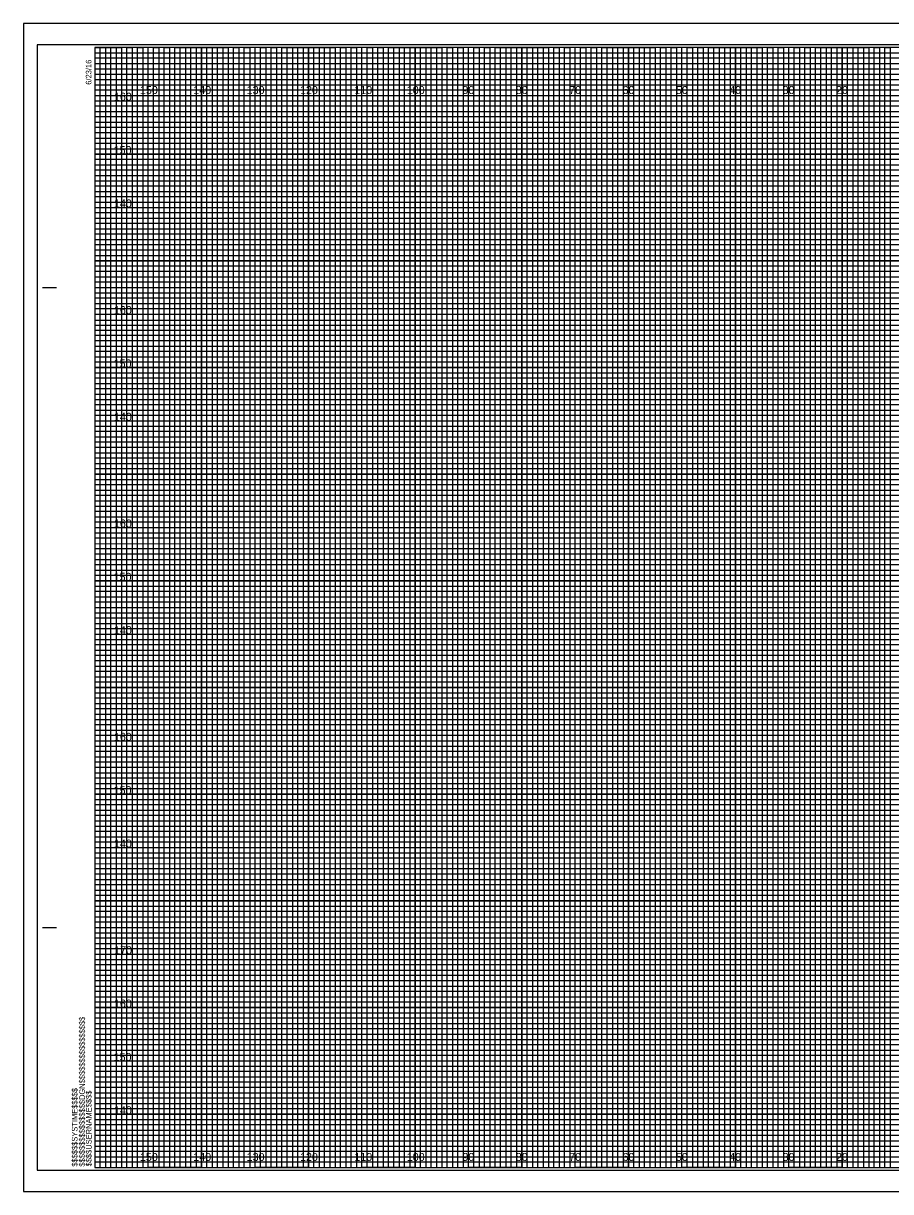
# Model space of a CAD drawing. Extents: x -13 to 323, y -5 to 4834.
# Drawn here: x -13.4 to 149.1, y 1315.5 to 1534.5 of the extents above; entities that cross this region are included whole.
import ezdxf

# ---------------------------------------------------------------- set-up
doc = ezdxf.new("R2010")
doc.units = 0
for name, color, linetype in [('Exist Cross Section Cell', 7, 'Continuous'), ('Exist XS Center Line Elevation Label', 7, 'Continuous'), ('Exist XS Ground Line', 7, 'Continuous'), ('Prop CMT Pvmt Course 1', 7, 'Continuous'), ('Prop CMT Pvmt Course 2', 7, 'Continuous'), ('Prop CMT Pvmt Course 3', 7, 'Continuous'), ('Prop CMT Pvmt Surface Shoulder', 7, 'Continuous'), ('Prop CMT Shld Paved Course 1', 7, 'Continuous'), ('Prop CMT Shld Paved Course 2', 7, 'Continuous'), ('Prop CMT Shld Paved Course 3', 7, 'Continuous'), ('Prop CMT Slope Grass', 7, 'Continuous')]:
    doc.layers.add(name, color=color, linetype=linetype)

msp = doc.modelspace()

# ---------------------------------------------------------------- linework, layer by layer
at = {"layer": 'Exist XS Center Line Elevation Label'}
for points in [[(0, 1530), (5, 1530), (5, 1320), (15, 1320), (15, 1530), (25, 1530), (25, 1320), (35, 1320), (35, 1530), (45, 1530), (45, 1320), (55, 1320), (55, 1530), (65, 1530), (65, 1320), (75, 1320), (75, 1530), (85, 1530), (85, 1320), (95, 1320), (95, 1530), (105, 1530), (105, 1320), (115, 1320), (115, 1530), (125, 1530), (125, 1320), (135, 1320), (135, 1530), (145, 1530), (145, 1320), (155, 1320)], [(0, 1525), (275, 1525)], [(0, 1505), (320, 1505), (320, 1515), (0, 1515)], [(0, 1485), (320, 1485), (320, 1495), (0, 1495)], [(0, 1465), (320, 1465), (320, 1475), (0, 1475)], [(0, 1445), (320, 1445), (320, 1455), (0, 1455)], [(0, 1425), (320, 1425), (320, 1435), (0, 1435)], [(0, 1405), (320, 1405), (320, 1415), (0, 1415)], [(0, 1385), (320, 1385), (320, 1395), (0, 1395)], [(0, 1365), (320, 1365), (320, 1375), (0, 1375)], [(0, 1345), (320, 1345), (320, 1355), (0, 1355)], [(0, 1325), (320, 1325), (320, 1335), (0, 1335)]]:
    msp.add_lwpolyline(points, dxfattribs=at)
at = {"layer": 'Exist XS Ground Line'}
for p, q in [((10, 1530), (0, 1530)), ((10, 1320), (10, 1530)), ((30, 1530), (20, 1530)), ((20, 1530), (20, 1320)), ((30, 1320), (30, 1530)), ((50, 1530), (40, 1530)), ((40, 1530), (40, 1320)), ((50, 1320), (50, 1530)), ((70, 1530), (60, 1530)), ((60, 1530), (60, 1320)), ((70, 1320), (70, 1530)), ((90, 1530), (80, 1530)), ((80, 1530), (80, 1320)), ((90, 1320), (90, 1530)), ((110, 1530), (100, 1530)), ((100, 1530), (100, 1320)), ((110, 1320), (110, 1530)), ((130, 1530), (120, 1530)), ((120, 1530), (120, 1320)), ((130, 1320), (130, 1530)), ((150, 1530), (140, 1530)), ((140, 1530), (140, 1320)), ((20, 1320), (10, 1320)), ((40, 1320), (30, 1320)), ((60, 1320), (50, 1320)), ((80, 1320), (70, 1320)), ((100, 1320), (90, 1320)), ((120, 1320), (110, 1320)), ((140, 1320), (130, 1320))]:
    msp.add_line(p, q, dxfattribs=at)
for points in [[(0, 1520), (320, 1520), (320, 1510), (0, 1510)], [(0, 1500), (320, 1500), (320, 1490), (0, 1490)], [(0, 1480), (320, 1480), (320, 1470), (0, 1470)], [(0, 1460), (320, 1460), (320, 1450), (0, 1450)], [(0, 1440), (320, 1440), (320, 1430), (0, 1430)], [(0, 1420), (320, 1420), (320, 1410), (0, 1410)], [(0, 1400), (320, 1400), (320, 1390), (0, 1390)], [(0, 1380), (320, 1380), (320, 1370), (0, 1370)], [(0, 1360), (320, 1360), (320, 1350), (0, 1350)], [(0, 1340), (320, 1340), (320, 1330), (0, 1330)]]:
    msp.add_lwpolyline(points, dxfattribs=at)
at = {"layer": 'Prop CMT Pvmt Course 1'}
for points in [[(0, 1320), (1, 1320), (1, 1530), (2, 1530), (2, 1320)], [(2, 1320), (3, 1320), (3, 1530), (4, 1530), (4, 1320)], [(5, 1320), (6, 1320), (6, 1530), (7, 1530), (7, 1320)], [(7, 1320), (8, 1320), (8, 1530), (9, 1530), (9, 1320)], [(10, 1320), (11, 1320), (11, 1530), (12, 1530), (12, 1320)], [(12, 1320), (13, 1320), (13, 1530), (14, 1530), (14, 1320)], [(15, 1320), (16, 1320), (16, 1530), (17, 1530), (17, 1320)], [(17, 1320), (18, 1320), (18, 1530), (19, 1530), (19, 1320)], [(20, 1320), (21, 1320), (21, 1530), (22, 1530), (22, 1320)], [(22, 1320), (23, 1320), (23, 1530), (24, 1530), (24, 1320)], [(25, 1320), (26, 1320), (26, 1530), (27, 1530), (27, 1320)], [(27, 1320), (28, 1320), (28, 1530), (29, 1530), (29, 1320)], [(30, 1320), (31, 1320), (31, 1530), (32, 1530), (32, 1320)], [(32, 1320), (33, 1320), (33, 1530), (34, 1530), (34, 1320)], [(35, 1320), (36, 1320), (36, 1530), (37, 1530), (37, 1320)], [(37, 1320), (38, 1320), (38, 1530), (39, 1530), (39, 1320)], [(40, 1320), (41, 1320), (41, 1530), (42, 1530), (42, 1320)], [(42, 1320), (43, 1320), (43, 1530), (44, 1530), (44, 1320)], [(45, 1320), (46, 1320), (46, 1530), (47, 1530), (47, 1320)], [(47, 1320), (48, 1320), (48, 1530), (49, 1530), (49, 1320)], [(50, 1320), (51, 1320), (51, 1530), (52, 1530), (52, 1320)], [(52, 1320), (53, 1320), (53, 1530), (54, 1530), (54, 1320)], [(55, 1320), (56, 1320), (56, 1530), (57, 1530), (57, 1320)], [(57, 1320), (58, 1320), (58, 1530), (59, 1530), (59, 1320)], [(60, 1320), (61, 1320), (61, 1530), (62, 1530), (62, 1320)], [(62, 1320), (63, 1320), (63, 1530), (64, 1530), (64, 1320)], [(65, 1320), (66, 1320), (66, 1530), (67, 1530), (67, 1320)], [(67, 1320), (68, 1320), (68, 1530), (69, 1530), (69, 1320)], [(70, 1320), (71, 1320), (71, 1530), (72, 1530), (72, 1320)], [(72, 1320), (73, 1320), (73, 1530), (74, 1530), (74, 1320)], [(75, 1320), (76, 1320), (76, 1530), (77, 1530), (77, 1320)], [(77, 1320), (78, 1320), (78, 1530), (79, 1530), (79, 1320)], [(80, 1320), (81, 1320), (81, 1530), (82, 1530), (82, 1320)], [(82, 1320), (83, 1320), (83, 1530), (84, 1530), (84, 1320)], [(85, 1320), (86, 1320), (86, 1530), (87, 1530), (87, 1320)], [(87, 1320), (88, 1320), (88, 1530), (89, 1530), (89, 1320)], [(90, 1320), (91, 1320), (91, 1530), (92, 1530), (92, 1320)], [(92, 1320), (93, 1320), (93, 1530), (94, 1530), (94, 1320)], [(95, 1320), (96, 1320), (96, 1530), (97, 1530), (97, 1320)], [(97, 1320), (98, 1320), (98, 1530), (99, 1530), (99, 1320)], [(100, 1320), (101, 1320), (101, 1530), (102, 1530), (102, 1320)], [(102, 1320), (103, 1320), (103, 1530), (104, 1530), (104, 1320)], [(105, 1320), (106, 1320), (106, 1530), (107, 1530), (107, 1320)], [(107, 1320), (108, 1320), (108, 1530), (109, 1530), (109, 1320)], [(110, 1320), (111, 1320), (111, 1530), (112, 1530), (112, 1320)], [(112, 1320), (113, 1320), (113, 1530), (114, 1530), (114, 1320)], [(115, 1320), (116, 1320), (116, 1530), (117, 1530), (117, 1320)], [(117, 1320), (118, 1320), (118, 1530), (119, 1530), (119, 1320)], [(120, 1320), (121, 1320), (121, 1530), (122, 1530), (122, 1320)], [(122, 1320), (123, 1320), (123, 1530), (124, 1530), (124, 1320)], [(125, 1320), (126, 1320), (126, 1530), (127, 1530), (127, 1320)], [(127, 1320), (128, 1320), (128, 1530), (129, 1530), (129, 1320)], [(130, 1320), (131, 1320), (131, 1530), (132, 1530), (132, 1320)], [(132, 1320), (133, 1320), (133, 1530), (134, 1530), (134, 1320)], [(135, 1320), (136, 1320), (136, 1530), (137, 1530), (137, 1320)], [(137, 1320), (138, 1320), (138, 1530), (139, 1530), (139, 1320)], [(140, 1320), (141, 1320), (141, 1530), (142, 1530), (142, 1320)], [(142, 1320), (143, 1320), (143, 1530), (144, 1530), (144, 1320)], [(145, 1320), (146, 1320), (146, 1530), (147, 1530), (147, 1320)], [(147, 1320), (148, 1320), (148, 1530), (149, 1530), (149, 1320)]]:
    msp.add_lwpolyline(points, dxfattribs=at)
at = {"layer": 'Prop CMT Pvmt Course 2'}
for p, q in [((323.3, 1534.5), (-13.4, 1534.5)), ((-13.4, 1534.5), (-13.4, 1315.5)), ((-13.4, 1315.5), (323.3, 1315.5))]:
    msp.add_line(p, q, dxfattribs=at)
at = {"layer": 'Prop CMT Pvmt Surface Shoulder'}
for p, q in [((-9.8, 1485), (-7.3, 1485)), ((-9.7, 1485), (-7.2, 1485)), ((-9.8, 1365), (-7.3, 1365)), ((-9.7, 1365), (-7.2, 1365)), ((0, 1320), (0, 1320)), ((0, 1320), (0, 1320)), ((0, 1320), (0, 1320)), ((0, 1320), (0, 1320)), ((0, 1320), (0, 1320)), ((0, 1320), (0, 1320)), ((0, 1320), (0, 1320))]:
    msp.add_line(p, q, dxfattribs=at)
msp.add_lwpolyline([(320, 1530), (0, 1530), (0, 1320), (320, 1320)], close=True, dxfattribs=at)
at = {"layer": 'Prop CMT Shld Paved Course 1'}
msp.add_lwpolyline([(-13.4, 1315.5), (323.3, 1315.5), (323.3, 1534.5), (-13.4, 1534.5)], close=True, dxfattribs=at)
at = {"layer": 'Prop CMT Shld Paved Course 2'}
msp.add_lwpolyline([(-10.8, 1319.5), (322.4, 1319.5), (322.4, 1530.5), (-10.8, 1530.5)], close=True, dxfattribs=at)
at = {"layer": 'Prop CMT Shld Paved Course 3'}
for p, q in [((10, 1320), (10, 1530)), ((20, 1320), (20, 1530)), ((30, 1320), (30, 1530)), ((40, 1320), (40, 1530)), ((50, 1320), (50, 1530)), ((60, 1320), (60, 1530)), ((70, 1320), (70, 1530)), ((80, 1320), (80, 1530)), ((90, 1320), (90, 1530)), ((100, 1320), (100, 1530)), ((110, 1320), (110, 1530)), ((120, 1320), (120, 1530)), ((130, 1320), (130, 1530)), ((140, 1320), (140, 1530)), ((0, 1520), (320, 1520)), ((0, 1510), (320, 1510)), ((0, 1500), (320, 1500)), ((0, 1490), (320, 1490)), ((0, 1480), (320, 1480)), ((0, 1470), (320, 1470)), ((0, 1460), (320, 1460)), ((0, 1450), (320, 1450)), ((0, 1440), (320, 1440)), ((0, 1430), (320, 1430)), ((0, 1420), (320, 1420)), ((0, 1410), (320, 1410)), ((0, 1400), (320, 1400)), ((0, 1390), (320, 1390)), ((0, 1380), (320, 1380)), ((0, 1370), (320, 1370)), ((0, 1360), (320, 1360)), ((0, 1350), (320, 1350)), ((0, 1340), (320, 1340)), ((0, 1330), (320, 1330))]:
    msp.add_line(p, q, dxfattribs=at)
at = {"layer": 'Prop CMT Slope Grass'}
for p, q in [((0, 1529), (260, 1529)), ((260, 1527.98), (0, 1527.98)), ((0, 1527.98), (0, 1527)), ((0, 1527), (260, 1527)), ((260, 1525.89), (0, 1525.89)), ((0, 1525.89), (0, 1524)), ((0, 1524), (320, 1524))]:
    msp.add_line(p, q, dxfattribs=at)
for points in [[(0, 1523), (270, 1523), (320, 1523), (320, 1522), (0, 1522)], [(0, 1521), (320, 1521), (320, 1519), (0, 1519)], [(0, 1518), (320, 1518), (320, 1517), (0, 1516.98)], [(0, 1516), (320, 1516), (320, 1514), (0, 1514)], [(0, 1513), (320, 1513), (320, 1512), (0, 1512)], [(0, 1511), (320, 1511), (320, 1509), (0, 1509)], [(0, 1508), (320, 1508), (320, 1507), (0, 1507)], [(0, 1506), (320, 1506), (320, 1504), (0, 1504)], [(0, 1503), (320, 1503), (320, 1502), (0, 1502)], [(0, 1501), (320, 1501), (320, 1499), (0, 1499)], [(0, 1498), (320, 1498), (320, 1497), (0, 1497)], [(0, 1496), (320, 1496), (320, 1493.95), (320, 1493), (320, 1492), (0, 1492)], [(0, 1494), (320, 1494), (320, 1493), (0, 1493)], [(0, 1491), (320, 1491), (320, 1489), (0, 1489.03)], [(0, 1489.03), (320, 1489), (320, 1488), (0, 1488)], [(0, 1487), (320, 1487), (320, 1486), (0, 1486)], [(0, 1484), (320, 1484), (320, 1483), (0, 1483)], [(0, 1482), (320, 1482), (320, 1481), (0, 1481)], [(-0.07, 1478.89), (320, 1478.89), (320, 1477.88), (-0.07, 1477.88)], [(0, 1477), (320, 1477), (320, 1476), (0, 1476)], [(0, 1474), (320, 1474), (320, 1473), (0, 1473)], [(0, 1472), (320, 1472), (320, 1471), (0, 1471)], [(0, 1469), (320, 1469), (320, 1468), (0, 1468)], [(0, 1467), (320, 1467), (320, 1466), (0, 1466)], [(0, 1464), (320, 1464), (320, 1463), (0, 1463)], [(0, 1462), (320, 1462), (320, 1461), (0, 1461)], [(0, 1459), (320, 1459), (319.99, 1457.98), (0, 1458)], [(0, 1457), (320, 1457), (320, 1456), (0, 1456)], [(0, 1454), (320, 1454), (320, 1453), (0, 1453)], [(0, 1452), (320, 1452), (320, 1451), (0, 1451)], [(0, 1449), (320, 1449), (320, 1448), (0, 1448)], [(0, 1447), (320, 1447), (320, 1446), (0, 1446)], [(0, 1444), (320, 1444), (320, 1443), (0, 1443)], [(0, 1442), (320, 1442), (320, 1441), (0, 1441)], [(0, 1439), (320, 1439), (320, 1438), (0, 1438)], [(0, 1436.99), (320.07, 1436.91), (320, 1436), (0, 1436)], [(0, 1434), (320, 1434), (320, 1433), (0, 1433)], [(0, 1432), (320, 1432), (320, 1431), (0, 1431)], [(0, 1429), (320, 1429), (320, 1428), (0, 1428)], [(0, 1427), (320, 1427), (320, 1426), (0, 1426)], [(0, 1424), (320, 1424), (320, 1423), (0, 1423)], [(0, 1422), (320, 1422), (320, 1421), (0, 1421)], [(0, 1419), (320, 1419), (320, 1418), (0, 1418)], [(0, 1417), (320, 1417), (320, 1416), (0, 1416)], [(0, 1414), (320, 1414), (320, 1413), (0, 1413)], [(0, 1412), (320, 1412), (320, 1411), (0, 1411)], [(0, 1409), (320, 1409), (320, 1408), (0, 1408)], [(0, 1407), (320, 1407), (320, 1406), (0, 1406)], [(0, 1404), (320, 1404), (320, 1403), (0, 1403)], [(0, 1402), (320, 1402), (320, 1401), (0, 1401)], [(0, 1399), (320, 1399), (319.99, 1397.98), (0, 1398)], [(0, 1397), (320, 1397), (320, 1396), (0, 1396)], [(0, 1394), (320, 1394), (320, 1393), (0, 1393)], [(0, 1392), (320, 1392), (320, 1391), (0, 1391)], [(0, 1389), (320, 1389), (320, 1388), (0, 1388)], [(0, 1387), (320, 1387), (320, 1386), (0, 1386)], [(0, 1384), (320, 1384), (320, 1383), (0, 1383)], [(0, 1382), (320, 1382), (320, 1381), (0, 1381)], [(0, 1379), (320, 1379), (320, 1378), (0, 1378)], [(0, 1376.99), (320.07, 1376.91), (320, 1376), (0, 1376)], [(0, 1374), (320, 1374), (320, 1373), (0, 1373)], [(0, 1372), (320, 1372), (320, 1371), (0, 1371)], [(0, 1369), (320, 1369), (320, 1368), (0, 1368)], [(0, 1367), (320, 1367), (320, 1366), (0, 1366)], [(0, 1364), (320, 1364), (320, 1363), (0, 1363)], [(0, 1362), (320, 1362), (320, 1361), (0, 1361)], [(0, 1359), (320, 1359), (320, 1358), (0, 1358)], [(0, 1357), (320, 1357), (320, 1356), (0, 1356)], [(0, 1354), (320, 1354), (320, 1353), (0, 1353)], [(0, 1352), (320, 1352), (320, 1351), (0, 1351)], [(0, 1349), (320, 1349), (320, 1348), (0, 1348)], [(0, 1347), (320, 1347), (320, 1346), (0, 1346)], [(0, 1344), (320, 1344), (320, 1343), (0, 1343)], [(0, 1342), (320, 1342), (320, 1341), (0, 1341)], [(0, 1339), (320, 1339), (320, 1338), (0, 1338)], [(0, 1337), (320, 1337), (320, 1336), (0, 1336)], [(0, 1334), (320, 1334), (320, 1333), (0, 1333)], [(0, 1332), (320, 1332), (320, 1331), (0, 1331)], [(0, 1329), (320, 1329), (320, 1328), (0, 1328)], [(0, 1327), (320, 1327), (320, 1326), (0, 1326)], [(0, 1324), (320, 1324), (320, 1323), (0, 1323)], [(0, 1322), (320, 1322), (320, 1321), (0, 1321)]]:
    msp.add_lwpolyline(points, dxfattribs=at)

# ---------------------------------------------------------------- texts
at = {"layer": 'Exist Cross Section Cell'}
for s, p in [('150', (8.44, 1521.25)), ('140', (18.44, 1521.25)), ('130', (28.44, 1521.25)), ('120', (38.44, 1521.25)), ('110', (48.62, 1521.25)), ('100', (58.44, 1521.25)), ('90', (68.86, 1521.25)), ('80', (78.86, 1521.25)), ('70', (88.86, 1521.25)), ('60', (98.86, 1521.25)), ('50', (108.86, 1521.25)), ('40', (118.86, 1521.25)), ('30', (128.86, 1521.25)), ('20', (138.86, 1521.25)), ('150', (8.44, 1321.25)), ('140', (18.44, 1321.25)), ('130', (28.44, 1321.25)), ('120', (38.44, 1321.25)), ('110', (48.62, 1321.25)), ('100', (58.44, 1321.25)), ('90', (68.86, 1321.25)), ('80', (78.86, 1321.25)), ('70', (88.86, 1321.25)), ('60', (98.86, 1321.25)), ('50', (108.86, 1321.25)), ('40', (118.86, 1321.25)), ('30', (128.86, 1321.25)), ('20', (138.86, 1321.25))]:
    msp.add_text(s, height=1.5, dxfattribs=at).set_placement(p)
at = {"layer": 'Prop CMT Pvmt Course 3'}
for s, p in [('160', (3.57, 1520)), ('150', (3.52, 1510)), ('140', (3.57, 1500)), ('160', (3.57, 1480)), ('150', (3.52, 1470)), ('140', (3.57, 1460)), ('160', (3.57, 1440)), ('150', (3.52, 1430)), ('140', (3.57, 1420)), ('160', (3.57, 1400)), ('150', (3.52, 1390)), ('140', (3.57, 1380)), ('170', (3.61, 1360)), ('160', (3.57, 1350)), ('150', (3.52, 1340)), ('140', (3.57, 1330))]:
    msp.add_text(s, height=1.5, dxfattribs=at).set_placement(p)
at = {"layer": 'Prop CMT Pvmt Surface Shoulder'}
for s, p in [('6/23/16', (-0.65, 1523)), ('$$$$$$$$$$$$$$$$DGN$$$$$$$$$$$$$$$$', (-1.88, 1320.18)), ('$$$$$$SYSTIME$$$$$', (-3.26, 1320.18)), ('$$$$USERNAME$$$$', (-0.62, 1320.23))]:
    msp.add_text(s, height=1.05, rotation=90, dxfattribs=at).set_placement(p)

doc.saveas('drawing.dxf')
